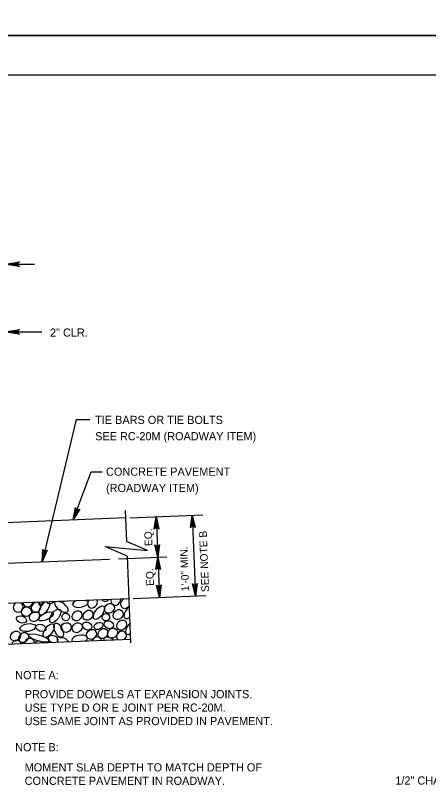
# Model space of a CAD drawing. Extents: x 638167 to 640248, y 296544 to 298920.
# Drawn here: x 638564 to 638719.6, y 296851.7 to 297146 of the extents above; entities that cross this region are included whole.
import ezdxf

# ---------------------------------------------------------------- set-up
doc = ezdxf.new("R2010")
doc.units = 0
doc.layers.add('1', color=7, linetype='Continuous')
doc.layers.add('PLT-BNDY', color=7, linetype='Continuous')

msp = doc.modelspace()

# ---------------------------------------------------------------- linework, layer by layer
at = {"layer": '1'}
for p, q in [((638991.78, 297123.48), (638205.78, 297123.48)), ((638540.19, 297052.34), (638571.06, 297052.34)), ((638543.97, 297026.78), (638573.88, 297026.78)), ((638586.76, 296993.82), (638573.93, 296940.17)), ((638586.76, 296993.82), (638591.98, 296993.82)), ((638585.69, 296955.9), (638592.47, 296974.1)), ((638592.47, 296974.1), (638596.54, 296974.1)), ((638605.3, 296959.5), (638605.77, 296947.74)), ((638605.42, 296956.69), (638469.25, 296951.25)), ((638607.02, 296956.76), (638634.5, 296957.86)), ((638616.93, 296957.15), (638618.15, 296926.7)), ((638630.53, 296957.7), (638631.75, 296927.24)), ((638602.8, 296941.32), (638620.93, 296942.05)), ((638605.99, 296942.2), (638607.3, 296909.54)), ((638523.23, 296938.14), (638599.37, 296941.19)), ((638608.24, 296926.3), (638635.72, 296927.4)), ((638606.63, 296926.24), (638286.36, 296913.43)), ((638271.73, 296897.59), (638607.24, 296911.01))]:
    msp.add_line(p, q, dxfattribs=at)
for points in [[(638560.68, 297052.34), (638565.38, 297053.22), (638565.2, 297053.09), (638565.02, 297052.97), (638564.92, 297052.81), (638564.83, 297052.65), (638564.8, 297052.49), (638564.78, 297052.34), (638564.8, 297052.18), (638564.83, 297052.02), (638564.92, 297051.86), (638565.02, 297051.71), (638565.2, 297051.58), (638565.38, 297051.45), (638560.68, 297052.34), (638565.2, 297051.58), (638565.02, 297051.71), (638560.68, 297052.34), (638564.92, 297051.86), (638564.83, 297052.02), (638560.68, 297052.34), (638564.8, 297052.18), (638564.78, 297052.34), (638560.68, 297052.34), (638564.8, 297052.49), (638564.83, 297052.65), (638560.68, 297052.34), (638564.92, 297052.81), (638565.02, 297052.97), (638560.68, 297052.34), (638565.2, 297053.09)], [(638560.68, 297026.78), (638565.38, 297027.66), (638565.2, 297027.53), (638565.02, 297027.41), (638564.92, 297027.25), (638564.83, 297027.09), (638564.8, 297026.93), (638564.78, 297026.78), (638564.8, 297026.62), (638564.83, 297026.46), (638564.92, 297026.3), (638565.02, 297026.15), (638565.2, 297026.02), (638565.38, 297025.9), (638560.68, 297026.78), (638565.2, 297026.02), (638565.02, 297026.15), (638560.68, 297026.78), (638564.92, 297026.3), (638564.83, 297026.46), (638560.68, 297026.78), (638564.8, 297026.62), (638564.78, 297026.78), (638560.68, 297026.78), (638564.8, 297026.93), (638564.83, 297027.09), (638560.68, 297026.78), (638564.92, 297027.25), (638565.02, 297027.41), (638560.68, 297026.78), (638565.2, 297027.53)], [(638585.69, 296955.9), (638586.5, 296960.61), (638586.56, 296960.4), (638586.61, 296960.19), (638586.73, 296960.04), (638586.84, 296959.9), (638586.98, 296959.82), (638587.12, 296959.74), (638587.27, 296959.71), (638587.43, 296959.68), (638587.61, 296959.71), (638587.79, 296959.75), (638587.97, 296959.87), (638588.15, 296960), (638585.69, 296955.9), (638587.97, 296959.87), (638587.79, 296959.75), (638585.69, 296955.9), (638587.61, 296959.71), (638587.43, 296959.68), (638585.69, 296955.9), (638587.27, 296959.71), (638587.12, 296959.74), (638585.69, 296955.9), (638586.98, 296959.82), (638586.84, 296959.9), (638585.69, 296955.9), (638586.73, 296960.04), (638586.61, 296960.19), (638585.69, 296955.9), (638586.56, 296960.4)], [(638616.93, 296957.15), (638618, 296952.49), (638617.87, 296952.67), (638617.73, 296952.85), (638617.57, 296952.93), (638617.41, 296953.02), (638617.25, 296953.04), (638617.09, 296953.06), (638616.94, 296953.03), (638616.78, 296953), (638616.63, 296952.9), (638616.47, 296952.8), (638616.36, 296952.61), (638616.24, 296952.42), (638616.93, 296957.15), (638616.36, 296952.61), (638616.47, 296952.8), (638616.93, 296957.15), (638616.63, 296952.9), (638616.78, 296953), (638616.93, 296957.15), (638616.94, 296953.03), (638617.09, 296953.06), (638616.93, 296957.15), (638617.25, 296953.04), (638617.41, 296953.02), (638616.93, 296957.15), (638617.57, 296952.93), (638617.73, 296952.85), (638616.93, 296957.15), (638617.87, 296952.67)], [(638630.53, 296957.7), (638631.6, 296953.04), (638631.47, 296953.21), (638631.33, 296953.39), (638631.17, 296953.48), (638631.01, 296953.56), (638630.85, 296953.59), (638630.69, 296953.61), (638630.54, 296953.57), (638630.38, 296953.54), (638630.23, 296953.44), (638630.08, 296953.34), (638629.96, 296953.15), (638629.84, 296952.97), (638630.53, 296957.7), (638629.96, 296953.15), (638630.08, 296953.34), (638630.53, 296957.7), (638630.23, 296953.44), (638630.38, 296953.54), (638630.53, 296957.7), (638630.54, 296953.57), (638630.69, 296953.61), (638630.53, 296957.7), (638630.85, 296953.59), (638631.01, 296953.56), (638630.53, 296957.7), (638631.17, 296953.48), (638631.33, 296953.39), (638630.53, 296957.7), (638631.47, 296953.21)], [(638605.99, 296942.2), (638597.67, 296945.87), (638613.73, 296944.34), (638605.77, 296947.74)], [(638573.93, 296940.17), (638574.16, 296944.94), (638574.24, 296944.74), (638574.32, 296944.53), (638574.45, 296944.4), (638574.59, 296944.28), (638574.73, 296944.21), (638574.88, 296944.15), (638575.04, 296944.14), (638575.2, 296944.13), (638575.37, 296944.19), (638575.55, 296944.24), (638575.71, 296944.39), (638575.88, 296944.53), (638573.93, 296940.17), (638575.71, 296944.39), (638575.55, 296944.24), (638573.93, 296940.17), (638575.37, 296944.19), (638575.2, 296944.13), (638573.93, 296940.17), (638575.04, 296944.14), (638574.88, 296944.15), (638573.93, 296940.17), (638574.73, 296944.21), (638574.59, 296944.28), (638573.93, 296940.17), (638574.45, 296944.4), (638574.32, 296944.53), (638573.93, 296940.17), (638574.24, 296944.74)], [(638617.54, 296941.93), (638616.47, 296946.58), (638616.6, 296946.41), (638616.74, 296946.23), (638616.9, 296946.15), (638617.06, 296946.06), (638617.22, 296946.04), (638617.38, 296946.02), (638617.53, 296946.05), (638617.69, 296946.08), (638617.84, 296946.18), (638618, 296946.28), (638618.11, 296946.47), (638618.23, 296946.65), (638617.54, 296941.93), (638618.11, 296946.47), (638618, 296946.28), (638617.54, 296941.93), (638617.84, 296946.18), (638617.69, 296946.08), (638617.54, 296941.93), (638617.53, 296946.05), (638617.38, 296946.02), (638617.54, 296941.93), (638617.22, 296946.04), (638617.06, 296946.06), (638617.54, 296941.93), (638616.9, 296946.15), (638616.74, 296946.23), (638617.54, 296941.93), (638616.6, 296946.41)], [(638617.54, 296941.93), (638618.61, 296937.27), (638618.48, 296937.44), (638618.34, 296937.62), (638618.18, 296937.71), (638618.02, 296937.79), (638617.86, 296937.81), (638617.7, 296937.83), (638617.55, 296937.8), (638617.39, 296937.77), (638617.24, 296937.67), (638617.08, 296937.57), (638616.97, 296937.38), (638616.85, 296937.2), (638617.54, 296941.93), (638616.97, 296937.38), (638617.08, 296937.57), (638617.54, 296941.93), (638617.24, 296937.67), (638617.39, 296937.77), (638617.54, 296941.93), (638617.55, 296937.8), (638617.7, 296937.83), (638617.54, 296941.93), (638617.86, 296937.81), (638618.02, 296937.79), (638617.54, 296941.93), (638618.18, 296937.71), (638618.34, 296937.62), (638617.54, 296941.93), (638618.48, 296937.44)], [(638618.15, 296926.7), (638617.08, 296931.36), (638617.21, 296931.18), (638617.35, 296931), (638617.51, 296930.92), (638617.67, 296930.83), (638617.83, 296930.81), (638617.99, 296930.79), (638618.14, 296930.82), (638618.3, 296930.86), (638618.45, 296930.96), (638618.61, 296931.06), (638618.72, 296931.24), (638618.84, 296931.43), (638618.15, 296926.7), (638618.72, 296931.24), (638618.61, 296931.06), (638618.15, 296926.7), (638618.45, 296930.96), (638618.3, 296930.86), (638618.15, 296926.7), (638618.14, 296930.82), (638617.99, 296930.79), (638618.15, 296926.7), (638617.83, 296930.81), (638617.67, 296930.83), (638618.15, 296926.7), (638617.51, 296930.92), (638617.35, 296931), (638618.15, 296926.7), (638617.21, 296931.18)], [(638631.75, 296927.24), (638630.68, 296931.9), (638630.81, 296931.72), (638630.95, 296931.55), (638631.11, 296931.46), (638631.27, 296931.37), (638631.43, 296931.35), (638631.59, 296931.33), (638631.74, 296931.37), (638631.9, 296931.4), (638632.05, 296931.5), (638632.21, 296931.6), (638632.32, 296931.79), (638632.44, 296931.97), (638631.75, 296927.24), (638632.32, 296931.79), (638632.21, 296931.6), (638631.75, 296927.24), (638632.05, 296931.5), (638631.9, 296931.4), (638631.75, 296927.24), (638631.74, 296931.37), (638631.59, 296931.33), (638631.75, 296927.24), (638631.43, 296931.35), (638631.27, 296931.37), (638631.75, 296927.24), (638631.11, 296931.46), (638630.95, 296931.55), (638631.75, 296927.24), (638630.81, 296931.72)]]:
    msp.add_lwpolyline(points, dxfattribs=at)
for centre, major_axis, ratio, start_param, end_param in [((638564.95, 296923), (-1.75, -0.78), 0.948581, 4.858014, 10.05193), ((638568.55, 296925), (-1.75, -0.78), 0.948581, 6.041055, 8.868889), ((638571.69, 296922.96), (1.29, 1.57), 0.844245, 0.812597, 6.758242), ((638574.79, 296922.72), (-1.76, -2.44), 0.479042, 3.984367, 9.301958), ((638573.68, 296927.66), (0.45, 4.03), 0.282192, 2.36721, 4.002176), ((638577.13, 296926.31), (1.29, 1.57), 0.844245, 2.937326, 4.633513), ((638581.2, 296923.22), (-2.44, 1.76), 0.479042, 6.144575, 11.609923), ((638582.01, 296927.05), (1.29, 1.57), 0.844245, 3.456732, 4.114107), ((638588.39, 296924.47), (-2.97, -0.48), 0.479042, 5.260141, 9.956857), ((638587.63, 296927.99), (-1.76, -2.44), 0.479042, 0.238343, 0.481611), ((638590.9, 296927.49), (1.29, 1.57), 0.844245, 3.627473, 3.943366), ((638592.96, 296924.62), (1.29, 1.57), 0.844245, 1.619643, 5.951196), ((638597.95, 296927.19), (1.29, 1.57), 0.844245, 2.967408, 4.603431), ((638601.73, 296925.65), (1.29, 1.57), 0.844245, 2.008108, 5.562731), ((638605.34, 296924.49), (1.29, 1.57), 0.844245, 1.11244, 4.773193), ((638605.34, 296924.49), (1.29, 1.57), 0.844245, 6.27398, 6.458399), ((638606.92, 296921.28), (-1.76, -2.44), 0.479042, 4.204006, 7.267307), ((638607.5, 296915.34), (-1.76, -2.44), 0.479042, 4.365569, 7.105744), ((638578.09, 296910.96), (1.88, -0.58), 0.646802, 5.825434, 10.881517), ((638582.11, 296909.74), (-2.44, 1.76), 0.479042, 4.285286, 7.186027), ((638588.1, 296911.01), (-2.97, -0.48), 0.479042, 2.351329, 6.582484), ((638594.5, 296909.96), (1.29, 1.57), 0.844245, 5.644884, 8.209141), ((638603.87, 296912.12), (1.29, 1.57), 0.844245, 4.644979, 9.209045), ((638564.16, 296908.69), (1.29, 1.57), 0.844245, 5.676034, 8.17799), ((638569.23, 296909.44), (-1.75, -0.78), 0.948581, 2.768835, 5.857924), ((638572.66, 296908.41), (-1.75, -0.78), 0.948581, 3.464469, 5.16229), ((638599.81, 296909.62), (-2.44, 1.76), 0.479042, 4.69169, 6.779622)]:
    msp.add_ellipse(centre, major_axis=major_axis, ratio=ratio, start_param=start_param, end_param=end_param, dxfattribs=at)
for centre, major_axis, ratio in [((638595.37, 296920.99), (-1.76, -2.44), 0.479042), ((638599.34, 296922.6), (1.29, 1.57), 0.844245), ((638568, 296921.33), (-1.75, -0.78), 0.948581), ((638571.07, 296919.46), (1.29, 1.57), 0.844245), ((638575.38, 296919.57), (2.71, 1.28), 0.422273), ((638578.9, 296919.76), (-1.76, -2.44), 0.479042), ((638582.87, 296919.37), (-0.06, 1.43), 0.982495), ((638587.09, 296919.8), (1.29, 1.57), 0.844245), ((638591.24, 296919.98), (1.29, 1.57), 0.844245), ((638597.98, 296919.26), (-0.06, 1.43), 0.982495), ((638602.59, 296920.23), (1.29, 1.57), 0.844245), ((638566.18, 296918.38), (1.88, -0.58), 0.646802), ((638599.1, 296916.4), (1.64, -0.76), 0.796199), ((638603.95, 296916.26), (1.29, 1.57), 0.844245), ((638568.56, 296915.34), (-2.97, -0.48), 0.479042), ((638573.48, 296915.24), (1.88, -0.58), 0.646802), ((638576.42, 296914.19), (-1.76, -2.44), 0.479042), ((638580.17, 296914.28), (1.23, -2.74), 0.479042), ((638583.03, 296915.36), (-1.75, -0.78), 0.948581), ((638587.17, 296915.31), (1.29, 1.57), 0.844245), ((638590.96, 296915.9), (1.64, -0.76), 0.796199), ((638592.55, 296912.8), (1.29, 1.57), 0.844245), ((638595.21, 296915.99), (1.59, 0.79), 0.687276), ((638596.93, 296913.11), (1.29, 1.57), 0.844245), ((638600.48, 296913.22), (1.29, 1.57), 0.844245), ((638563.91, 296912.17), (1.29, 1.57), 0.844245), ((638566.96, 296911.61), (1.29, 1.57), 0.844245), ((638572.69, 296911.42), (3.89, -1.14), 0.282192)]:
    msp.add_ellipse(centre, major_axis=major_axis, ratio=ratio, dxfattribs=at)
at = {"layer": 'PLT-BNDY'}
for points in [[(638166.78, 297732.48), (639007.78, 297732.48), (639007.78, 297138.48), (638166.78, 297138.48)], [(638166.78, 297138.48), (639007.78, 297138.48), (639007.78, 296544.48), (638166.78, 296544.48)]]:
    msp.add_lwpolyline(points, close=True, dxfattribs=at)

# ---------------------------------------------------------------- texts
at = {"layer": '1'}
for s, p in [('2" CLR.', (638576.93, 297025)), ('TIE BARS OR TIE BOLTS', (638593.94, 296992.08)), ('SEE RC-20M (ROADWAY ITEM)', (638593.94, 296985.93)), ('CONCRETE PAVEMENT', (638598.05, 296972.57)), ('(ROADWAY ITEM)', (638598.05, 296966.42)), ('NOTE A:', (638563.78, 296895.9)), ('PROVIDE DOWELS AT EXPANSION JOINTS.', (638567.37, 296888.74)), ('USE TYPE D OR E JOINT PER RC-20M.', (638567.37, 296883.66)), ('USE SAME JOINT AS PROVIDED IN PAVEMENT.', (638567.37, 296878.59)), ('NOTE B:', (638563.78, 296868.75)), ('MOMENT SLAB DEPTH TO MATCH DEPTH OF', (638567.37, 296861.14)), ('CONCRETE PAVEMENT IN ROADWAY.', (638567.37, 296856.07)), ('1/2" CHAMFER', (638707.11, 296856.19))]:
    msp.add_text(s, height=3.072, dxfattribs=at).set_placement(p)
for s, p in [('EQ.', (638615.53, 296946.13)), ('SEE NOTE B', (638636.91, 296928.78)), ('1\'-0" MIN.', (638629.41, 296929.1)), ('EQ.', (638616.13, 296931.11))]:
    msp.add_text(s, height=2.88, rotation=92.2906, dxfattribs=at).set_placement(p)

doc.saveas('drawing.dxf')
